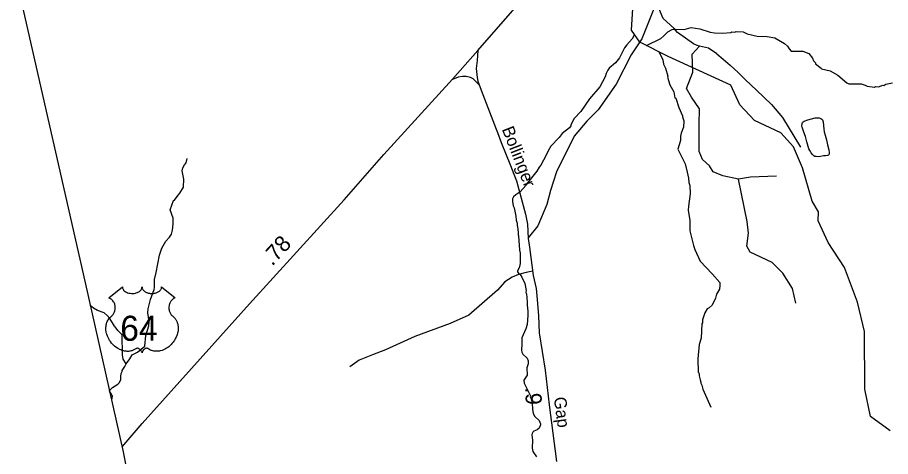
# Model space of a CAD drawing. Extents: x 1113032 to 1302912, y 664689 to 832535.
# Drawn here: x 1158104 to 1164889, y 682356 to 685772 of the extents above; entities that cross this region are included whole.
import ezdxf

# ---------------------------------------------------------------- set-up
doc = ezdxf.new("R2010")
doc.units = 0
for name, color, linetype in [('Exist Boundary Political CountyLine', 7, 'Continuous'), ('Exist Hydrographic Creek Single Shore', 7, 'Continuous'), ('Exist Hydrographic Misc Water Feature', 7, 'Continuous'), ('Exist Road Non-System Type 51', 7, 'Continuous'), ('Exist Road Primary US Attributed', 7, 'Continuous'), ('Exist Road Primary US Mileage Hundredths English Label', 7, 'Continuous'), ('Exist Road Primary US Shield CELL', 7, 'Continuous'), ('Exist Road Primary US Shield Number Label', 7, 'Continuous'), ('Exist Road Secondary Mileage Hundredths English Label', 7, 'Continuous'), ('Exist Road Secondary Type 51 Attributed', 7, 'Continuous'), ('Exist Road Secondary Type 51 Label', 7, 'Continuous')]:
    doc.layers.add(name, color=color, linetype=linetype)

msp = doc.modelspace()

# ---------------------------------------------------------------- linework, layer by layer
at = {"layer": 'Exist Boundary Political CountyLine'}
msp.add_lwpolyline([(1148404.8, 729149.7), (1156119.1, 694505), (1156385.7, 693318.6), (1156931.2, 691025.8), (1157283.7, 689488.8), (1157952.7, 686675.9), (1158627.6, 683719.1), (1158926.2, 682391.3), (1158990.6, 682053.6), (1159297.9, 680748.3), (1159630.3, 679269.8), (1159949.4, 677817.9), (1160303.4, 676324.9), (1160338.1, 676139.7)], dxfattribs=at)
at = {"layer": 'Exist Hydrographic Creek Single Shore'}
msp.add_lwpolyline([(1164887.3, 682555.8), (1164733.9, 682668.1), (1164689.9, 682879), (1164685.9, 683328.8), (1164633.8, 683556.3), (1164532.8, 683827.5), (1164404.9, 684020.4), (1164326.8, 684189.4), (1164328.9, 684258.2), (1164280.8, 684341.3), (1164204.8, 684602.1), (1164134.8, 684764.4), (1164037.8, 684874.6), (1163831.8, 684970.6), (1163718.9, 685091.1), (1163647.8, 685243.5), (1163161.8, 685466.6), (1162939.9, 685579.4), (1162875.8, 685672.6), (1162889.8, 685882.4)], dxfattribs=at)
at = {"layer": 'Exist Hydrographic Misc Water Feature'}
for points in [[(1162993.4, 685552.2), (1163103.7, 685608.4), (1163128.6, 685629.3), (1163157.9, 685660), (1163192.7, 685676.5), (1163218.9, 685681.4), (1163284.9, 685678.5), (1163340.7, 685692.5), (1163406.9, 685682.9), (1163488.3, 685657.7), (1163520.1, 685652.3), (1163584, 685649.6), (1163648.4, 685654.8), (1163656.5, 685658.4), (1163680.5, 685657.4), (1163688.7, 685661.1), (1163744.7, 685658.6), (1163776.2, 685645.3), (1163852.5, 685625.2), (1163931.4, 685622.5), (1163991, 685611.9), (1164065.3, 685568.7), (1164088.4, 685547.7), (1164101.6, 685527.1), (1164116.9, 685510.4), (1164207, 685510.5), (1164254.2, 685490.5), (1164282.8, 685455.2), (1164291.9, 685434.8), (1164305.2, 685418.2), (1164306.8, 685410.2), (1164351.1, 685377.8), (1164353.3, 685372.1), (1164420.8, 685357.2), (1164479.3, 685322.3), (1164548.9, 685263.6), (1164564.6, 685254.9), (1164660.7, 685254.7), (1164692.3, 685245.4), (1164708, 685236.7), (1164763.8, 685230.3), (1164771.9, 685233.9), (1164795.9, 685232.9), (1164828.4, 685243.5), (1164836.4, 685243.2), (1164852.8, 685252.4), (1164905.4, 685264.2)], [(1162898.5, 685639.6), (1162881.2, 685604), (1162839.2, 685557.8), (1162822.2, 685534.5), (1162782.8, 685456.2), (1162751.1, 685417.6), (1162703.3, 685377.6), (1162692.7, 685362), (1162679.6, 685336.6), (1162672.4, 685308.9), (1162629, 685230.7), (1162548.9, 685138.2), (1162482.6, 685039), (1162430.2, 684985.2), (1162404.2, 684936.3), (1162403.8, 684928.3), (1162393.1, 684912.8), (1162337.2, 684869.2), (1162313.8, 684838.2), (1162248.8, 684769), (1162225.1, 684730), (1162213.8, 684700.4), (1162170.4, 684622.3), (1162157.8, 684606.8), (1162140.4, 684575.6), (1162068.4, 684484.6), (1162057.6, 684467.1), (1162007.3, 684413.3), (1161976.4, 684392.5), (1161959.7, 684377.3), (1161951, 684361.6), (1161950.1, 684339.7), (1161956.7, 684307.4), (1161964, 684291), (1161977.4, 684226.5), (1161979.9, 684194.3), (1161986.9, 684170), (1161986.3, 684154), (1161989.9, 684145.9), (1161995.8, 684097.6), (1161995.2, 684081.6), (1161998.8, 684073.4), (1162006.1, 683961.1), (1162011, 683936.8), (1162009.7, 683856.8), (1162004.2, 683825.1), (1161991.2, 683801.6), (1161990.9, 683793.6), (1162000.2, 683777.2), (1162010, 683770.8), (1162025.1, 683752.1), (1162047.2, 683703.2), (1162056.7, 683646.7), (1162056.1, 683630.7), (1162059.7, 683622.6), (1162065, 683558.3), (1162064, 683534.4), (1162069.9, 683486.1), (1162070.6, 683454), (1162065.5, 683382.2), (1162056.1, 683350.6), (1162025, 683279.9), (1162025, 683231.9), (1162020.9, 683184), (1162024.3, 683167.9), (1162031.6, 683151.6), (1162064.4, 683122.1), (1162073.5, 683101.7), (1162072.5, 683077.8), (1162063.2, 683046.1), (1162064.8, 682990), (1162039.1, 682951.1), (1162042, 682927), (1162089.9, 682828.9), (1162089.6, 682820.9), (1162096.9, 682804.6), (1162103.6, 682772.3), (1162105.5, 682724.1), (1162112.2, 682691.8), (1162125.1, 682667.3), (1162157.8, 682635.9), (1162168.7, 682609.4), (1162168.4, 682601.4), (1162157.3, 682577.8), (1162142.7, 682564.5), (1162118.2, 682553.5), (1162109.9, 682545.9), (1162103.5, 682536.2), (1162101, 682524.3), (1162107.3, 682484), (1162104.6, 682420), (1162109.5, 682395.8), (1162137.8, 682354.6)], [(1163091.3, 685502.4), (1163118.6, 685441.6), (1163125.2, 685409.3), (1163139.9, 685376.7), (1163158.8, 685313.8), (1163156.9, 685307.9), (1163173.5, 685248), (1163204.2, 685193.8), (1163214.1, 685145.3), (1163220, 685143.1), (1163243, 685072), (1163272.3, 685006.8), (1163272, 684998.8), (1163282.6, 684966.3), (1163280.6, 684918.4), (1163262.5, 684871.1), (1163257.6, 684849.3), (1163256.1, 684815.4), (1163237.2, 684748.2), (1163292.5, 684633.7), (1163309.7, 684568.9), (1163319.6, 684520.4), (1163322.3, 684488.4), (1163329.3, 684464), (1163332.5, 684399.8), (1163318.4, 684304.4), (1163317.1, 684272.4), (1163329.7, 684191.5), (1163330.2, 684111.8), (1163357.5, 683998.6), (1163368.1, 683966.1), (1163410.3, 683876.2), (1163502.2, 683778.2), (1163561.4, 683709.6), (1163563.9, 683687.2), (1163559.2, 683658), (1163536.9, 683619.2), (1163528.7, 683588.5), (1163503.9, 683534.3), (1163478.7, 683512.9), (1163464.5, 683503.7), (1163445.1, 683472.5), (1163428.8, 683419.2), (1163427.8, 683395.2), (1163423.5, 683387.4), (1163418.8, 683275.6), (1163402.7, 683228.2), (1163391.9, 683116.7), (1163395.3, 683008.4), (1163399.3, 683008.3), (1163402.8, 682996.1), (1163402.3, 682984.1), (1163408.9, 682951.8), (1163416.2, 682935.5), (1163415.9, 682927.5), (1163423.2, 682911.2), (1163429.8, 682878.9), (1163492, 682740.1)], [(1164217, 684963.6), (1164246.1, 684975.9), (1164275.4, 684983.9), (1164303.3, 684990.1), (1164318.6, 684991), (1164334.5, 684989.7), (1164347.1, 684986.2), (1164354.9, 684980.7), (1164360.1, 684974.8), (1164362.9, 684968.1), (1164366.2, 684958.3), (1164368.5, 684931), (1164371.2, 684902.3), (1164374.6, 684882.9), (1164380.9, 684855.8), (1164390.9, 684820.3), (1164399.9, 684781.8), (1164408.6, 684742), (1164411.9, 684721.1), (1164411.6, 684711), (1164410.1, 684703.6), (1164406, 684699.8), (1164399.8, 684697.8), (1164383.4, 684696), (1164367.1, 684694.7), (1164344.2, 684690.1), (1164327.4, 684688.4), (1164312.4, 684689.3), (1164302.3, 684690.9), (1164294.5, 684695.1), (1164282, 684705.6), (1164273.1, 684717.2), (1164261.3, 684736.1), (1164255.5, 684749.4), (1164249.8, 684767.2), (1164238.6, 684805), (1164227.4, 684844.4), (1164215.2, 684880), (1164202.6, 684917.8), (1164201.1, 684928.4), (1164202.5, 684945.9), (1164204.9, 684953.8), (1164211.3, 684960.2), (1164217, 684963.6)], [(1158948.2, 683077.6), (1158978.1, 683115.8), (1158995.4, 683147.1), (1159037.7, 683168.5), (1159094.4, 683214.8), (1159102, 683298.5), (1159125.2, 683373.5), (1159126.6, 683405.5), (1159117.5, 683473.9), (1159118.8, 683505.9), (1159137.9, 683577.1), (1159165.3, 683655.9), (1159167.9, 683671.8), (1159168.6, 683731.8), (1159182.9, 683787.2), (1159206.7, 683922.3), (1159227.1, 683977.4), (1159257.4, 684032.1), (1159286.8, 684062.9), (1159299.8, 684086.3), (1159309.1, 684117.9), (1159315.2, 684165.7), (1159312.8, 684203.8), (1159315.1, 684209.7), (1159291.8, 684274.7), (1159317.8, 684346.8), (1159323.1, 684349.4), (1159359.9, 684400.6), (1159365.4, 684403.6), (1159395.4, 684450.4), (1159398.2, 684514.3), (1159384.9, 684578.9), (1159389.9, 684602.7), (1159402.9, 684626.1), (1159415.6, 684641.6), (1159423, 684673.3)], [(1158948.2, 683077.6), (1158925.9, 683114), (1158919.3, 683148.3), (1158917.9, 683302.5), (1158883.3, 683336), (1158864.5, 683364.8), (1158858.7, 683369.1), (1158821.2, 683430.7), (1158802.2, 683453.6), (1158779, 683472.6), (1158725.7, 683492.9), (1158694.5, 683510.3), (1158669.8, 683531.2)], [(1158835.3, 682795.3), (1158838.3, 682797.7), (1158841.5, 682825.5), (1158834.2, 682841.9), (1158819.9, 682864), (1158827.8, 682878.2), (1158842.4, 682893.6), (1158883.4, 682917.8), (1158898.1, 682931.1), (1158907.1, 682954.8), (1158906.1, 682978.8), (1158909.2, 683002.7), (1158917.8, 683018.3), (1158918.2, 683026.3), (1158939.5, 683057.4), (1158948.2, 683077.6)]]:
    msp.add_lwpolyline(points, dxfattribs=at)
at = {"layer": 'Exist Road Non-System Type 51'}
for points in [[(1163062.1, 685905.1), (1163045.7, 685825.4), (1162957.6, 685603.9), (1162874, 685480.2), (1162757.5, 685253.1), (1162617.6, 685053.1), (1162529.2, 684963.6), (1162431.7, 684848.1), (1162293.8, 684569.9), (1162245.6, 684425.1), (1162218.5, 684316), (1162147.9, 684149.7), (1162072.9, 684058.4)], [(1163405.4, 685549), (1163386.1, 685552.7), (1163358.4, 685567.2), (1163234.8, 685655), (1163204.9, 685688.3), (1163122.7, 685762.4), (1163062.1, 685905.1)], [(1163707, 684513.9), (1163585.8, 684539.3), (1163510.6, 684569.4), (1163483, 684617.7), (1163427.5, 684666), (1163403.1, 684728.8), (1163403.1, 684940.8), (1163403.6, 685059.9), (1163341.8, 685152.6), (1163303.9, 685219.7), (1163352.3, 685347.1), (1163347.5, 685484.8), (1163405.4, 685549)], [(1163539.4, 685489.6), (1163474.2, 685533.1), (1163405.4, 685549)], [(1163539.4, 685489.6), (1163587.7, 685447.4), (1163642, 685400.3), (1163705.9, 685343.5), (1163762.7, 685285.5)], [(1161693.2, 685247.9), (1161646.2, 685293.7), (1161623.8, 685305.6), (1161591, 685312.7), (1161562.2, 685312.3), (1161529.1, 685307.5), (1161484.2, 685289.4)], [(1163762.7, 685285.5), (1163847, 685206), (1163963.1, 685094.8), (1164048.9, 684993.8), (1164190.3, 684761.4)], [(1164001.9, 684537.6), (1163801.5, 684529.1), (1163707, 684513.9)], [(1164154, 683549.2), (1164127.5, 683662.7), (1164052.6, 683783.5), (1163970.6, 683865.6), (1163799.2, 683945.3), (1163772.7, 683993.6), (1163785.2, 684093.5), (1163773.9, 684183.7), (1163707, 684513.9)], [(1162108.4, 683797.2), (1162058.4, 683786.3), (1161999.1, 683771.9), (1161949.2, 683750.2), (1161891.6, 683715.7), (1161834, 683649.8), (1161612.7, 683455.2), (1161466, 683390.7), (1161191.7, 683289.3), (1160963.5, 683187.2), (1160864.5, 683148.2), (1160759.5, 683106.1), (1160686.5, 683053.7)]]:
    msp.add_lwpolyline(points, dxfattribs=at)
at = {"layer": 'Exist Road Primary US Attributed'}
for points in [[(1161681.9, 685515.3), (1161950.5, 685821.9), (1162036.9, 685921.5), (1162078.6, 685967.9), (1162313.4, 686262.8), (1162342.6, 686301.4)], [(1158917.1, 682431.3), (1159073.7, 682612.8), (1159906.7, 683544.1), (1160642.9, 684353.9), (1160952, 684704.9), (1161485.8, 685291.1), (1161681.9, 685515.3)]]:
    msp.add_lwpolyline(points, dxfattribs=at)
at = {"layer": 'Exist Road Primary US Shield CELL'}
msp.add_lwpolyline([(1158920, 683674.9), (1158920.3, 683670.5), (1158921.3, 683665.3), (1158922.1, 683662.6), (1158924.6, 683657.5), (1158928.6, 683651.4), (1158934.2, 683645.4), (1158940.6, 683640.2), (1158944.8, 683637.4), (1158952.1, 683633.5), (1158960.3, 683630.1), (1158969.5, 683627.4), (1158978.8, 683625.6), (1158989.1, 683624.4), (1158999.2, 683624.2), (1159010.1, 683625), (1159022.1, 683627.4), (1159027.7, 683628.8), (1159033.9, 683631), (1159039.7, 683633.3), (1159046.1, 683636.7), (1159051.1, 683640), (1159055.1, 683642.9), (1159060.8, 683648.3), (1159065.3, 683653.9), (1159067.1, 683657), (1159068.8, 683660), (1159071, 683666.4), (1159071.6, 683669.3), (1159072.1, 683675.1), (1159072.4, 683670.2), (1159072.9, 683667.1), (1159073.8, 683664.1), (1159075, 683660.9), (1159077.3, 683656.4), (1159079.8, 683652.6), (1159084.5, 683647), (1159087.5, 683644.3), (1159090.2, 683642.1), (1159097.4, 683637.1), (1159105.8, 683632.8), (1159110, 683631), (1159114.2, 683629.5), (1159119.6, 683627.9), (1159125.2, 683626.6), (1159130.8, 683625.6), (1159136.4, 683624.8), (1159142.2, 683624.4), (1159146.9, 683624.2), (1159152.7, 683624.3), (1159158, 683624.6), (1159163.5, 683625.2), (1159169.5, 683626.2), (1159174.3, 683627.3), (1159180.7, 683629), (1159186.5, 683631.1), (1159191.6, 683633.3), (1159198.2, 683636.7), (1159203.5, 683640.1), (1159207.4, 683643.2), (1159212, 683647.5), (1159216.4, 683652.6), (1159219, 683656.3), (1159220.8, 683660.1), (1159222.5, 683664.1), (1159223.6, 683668.4), (1159224.1, 683672.1), (1159224.2, 683675.2), (1159330.4, 683590.6), (1159327.9, 683589.6), (1159322.2, 683586.8), (1159317.6, 683584.1), (1159310.3, 683579), (1159307.1, 683576.1), (1159304, 683573.2), (1159301.1, 683570), (1159298.6, 683567.1), (1159295.5, 683562.8), (1159292.7, 683558.5), (1159290, 683553.8), (1159288, 683549.8), (1159284.8, 683541.2), (1159283.2, 683535.8), (1159282.2, 683531.2), (1159281, 683521.7), (1159280.6, 683517.2), (1159280.6, 683512.8), (1159280.9, 683508.1), (1159281.3, 683503.5), (1159282.1, 683498.8), (1159282.9, 683494.7), (1159284.2, 683489.6), (1159286.1, 683483.7), (1159288.4, 683478), (1159293.3, 683468.7), (1159299.5, 683459.3), (1159304, 683454), (1159308.4, 683449.5), (1159314.9, 683444), (1159318.5, 683440.9), (1159322.6, 683436.8), (1159329.2, 683429.1), (1159331.9, 683425.4), (1159334.7, 683421.3), (1159337.2, 683417.1), (1159339.7, 683412.6), (1159341.7, 683408.6), (1159345.4, 683399.5), (1159348.1, 683390.7), (1159349.4, 683386), (1159351.4, 683375.6), (1159352.1, 683370.5), (1159352.9, 683360.3), (1159353, 683348), (1159352, 683336.3), (1159349.8, 683322.7), (1159348, 683314.5), (1159345.2, 683305), (1159342.5, 683296.8), (1159337.7, 683284.7), (1159333.4, 683275.9), (1159327.8, 683265.6), (1159324, 683259.4), (1159319.5, 683252.7), (1159313.9, 683245), (1159307.4, 683236.9), (1159299.5, 683228.3), (1159293.2, 683221.9), (1159284.9, 683214.5), (1159279.9, 683210.4), (1159272.7, 683205), (1159262.9, 683198.5), (1159253.3, 683192.9), (1159245.1, 683188.7), (1159237.8, 683185.5), (1159228.4, 683181.9), (1159212.7, 683177.6), (1159207, 683176.4), (1159200.2, 683175.4), (1159193.8, 683174.8), (1159187.7, 683174.4), (1159179.4, 683174.4), (1159171.2, 683175), (1159163.4, 683176.2), (1159155.3, 683177.9), (1159146.8, 683180.4), (1159139.1, 683183.4), (1159131.4, 683187.2), (1159118.2, 683195.5), (1159114.4, 683197.5), (1159112.3, 683198.1), (1159107.2, 683198.3), (1159102.4, 683197.3), (1159097.5, 683195.4), (1159094.6, 683193.8), (1159090.6, 683191.2), (1159087.6, 683188.8), (1159084, 683185.4), (1159081.5, 683182.5), (1159079.6, 683180.2), (1159075.9, 683174.4), (1159074.5, 683171.6), (1159073.2, 683168.1), (1159072, 683162.8), (1159070.3, 683169.4), (1159068.3, 683173.8), (1159066.1, 683177.6), (1159063.7, 683180.9), (1159060, 683185.2), (1159056.7, 683188.4), (1159052.7, 683191.7), (1159048.4, 683194.2), (1159045, 683196), (1159041.8, 683197.2), (1159038, 683198.1), (1159034.9, 683198.4), (1159032.3, 683198.3), (1159028.8, 683197.5), (1159024, 683194.1), (1159019.4, 683190.9), (1159014.4, 683187.8), (1159008.5, 683184.7), (1159004.2, 683182.7), (1158999.1, 683180.7), (1158993, 683178.7), (1158986.5, 683177), (1158979.8, 683175.7), (1158973.9, 683174.7), (1158967.6, 683174.1), (1158961.9, 683174), (1158955.9, 683174), (1158950.3, 683174.5), (1158943.8, 683175), (1158935.8, 683176.2), (1158929.2, 683177.7), (1158922.1, 683179.6), (1158914.9, 683181.9), (1158907.2, 683184.8), (1158897.5, 683189), (1158890.8, 683192.5), (1158880.2, 683198.6), (1158867.8, 683207.2), (1158858.4, 683214.8), (1158851.5, 683221), (1158841.4, 683231.3), (1158835.5, 683238), (1158826.2, 683250.1), (1158820.2, 683258.8), (1158816.3, 683265.2), (1158810.7, 683275.5), (1158807.6, 683282), (1158803.6, 683291.4), (1158800.4, 683300), (1158797.8, 683308.2), (1158796.3, 683313.4), (1158794.3, 683322.5), (1158793.1, 683328.9), (1158791.9, 683337.8), (1158791.3, 683347.2), (1158791.1, 683355.8), (1158791.4, 683362.9), (1158792.2, 683371.3), (1158793.6, 683380.1), (1158795.3, 683387.7), (1158796.8, 683393.2), (1158799.1, 683399.8), (1158802.1, 683407.2), (1158805.6, 683414.2), (1158808.9, 683420.1), (1158813.1, 683426.3), (1158817.3, 683431.7), (1158822.7, 683437.6), (1158828.4, 683443), (1158833.5, 683447.2), (1158839.7, 683453.2), (1158842.9, 683456.9), (1158846.7, 683462), (1158849.8, 683466.7), (1158852.3, 683470.9), (1158855.5, 683477.1), (1158857.4, 683481.7), (1158859.9, 683488.9), (1158861.1, 683493.9), (1158862.4, 683500.4), (1158863.2, 683506.5), (1158863.5, 683514.1), (1158863.3, 683520.4), (1158862.5, 683527.7), (1158861.1, 683534.7), (1158859.5, 683540.9), (1158856.8, 683547.9), (1158854.4, 683553.1), (1158850.3, 683560), (1158845.8, 683566.5), (1158841.1, 683571.8), (1158836.4, 683576.5), (1158831.9, 683580), (1158827.6, 683583.1), (1158822.2, 683586.4), (1158817, 683588.9), (1158813.7, 683590.3)], close=True, dxfattribs=at)
at = {"layer": 'Exist Road Secondary Type 51 Attributed'}
msp.add_lwpolyline([(1161681.9, 685515.3), (1161676.1, 685436), (1161669.9, 685373.6), (1161675.9, 685303.9), (1161683.1, 685275.1), (1161708.3, 685206.7), (1161824.7, 684903.6), (1161835.5, 684877.1), (1161863.1, 684799.1), (1161935.1, 684619.8), (1161961.3, 684552.9), (1161982.9, 684501.3), (1162052.2, 684240.6), (1162068.7, 684163), (1162073.7, 684052.6), (1162082.4, 683984.3), (1162112.9, 683764.4), (1162134.1, 683661.9), (1162143.6, 683577.1), (1162153.2, 683449.8), (1162158.4, 683319.1), (1162205.2, 683027.4), (1162235.6, 682758.3), (1162293.4, 682317.3)], dxfattribs=at)

# ---------------------------------------------------------------- texts
at = {"layer": 'Exist Road Primary US Mileage Hundredths English Label'}
msp.add_text('.78', height=125, rotation=47.72268, dxfattribs=at).set_placement((1160084.2, 683832.3))
at = {"layer": 'Exist Road Primary US Shield Number Label'}
msp.add_text('64', height=195, dxfattribs=at).set_placement((1158902.9, 683256.2))
at = {"layer": 'Exist Road Secondary Mileage Hundredths English Label'}
msp.add_text('.9', height=125, rotation=272.59515, dxfattribs=at).set_placement((1162049.2, 682894.5))
at = {"layer": 'Exist Road Secondary Type 51 Label'}
for s, rotation, p in [('Bollinger', 291.35735, (1161867.3, 684902.8)), ('Gap', 277.72898, (1162272.1, 682813.8))]:
    msp.add_text(s, height=95, rotation=rotation, dxfattribs=at).set_placement(p)

doc.saveas('drawing.dxf')
